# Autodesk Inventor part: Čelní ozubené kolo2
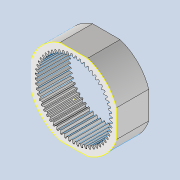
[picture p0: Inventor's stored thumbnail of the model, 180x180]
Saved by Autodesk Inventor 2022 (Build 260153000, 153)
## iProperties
CustomPartVersion: 1
Created: 2025-05
Part Number: Čelní ozubené kolo2
Material: Všeobecné
Document SubType Name: Modeling
Designer: jbart
Categories: <?xml version="1.0" encoding="UTF-16"?> <MemberInstance><Categories><FamilyTemplate><FamilyTemplateParameter ValueType="xs:double" Id="1" ObjectReferenceKey="da
Density: 1 g/cm^3
Appearance: Výchozí
Mass: 5402.18 g
Surface Area: 5816 cm^2
Volume: 5402.18 cm^3
Author: jbart
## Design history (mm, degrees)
sketch "Sketch1"
  geometry: C1 r 205 at (0, 0)
  constraints: 1 centre point
  dimensions: "d0" = 410 diameter of C1
extrude "Extrusion1" new body sketch "Sketch1" distance "d1" = 150 (= da_b); taper "d2" = 0 deg
workplane "Work Plane2"
sketch "Sketch2"
  geometry: C1 r 205 at (0, 0) reference; C2 r 171 at (0, 0)
  constraints: 1 centre point, 1 coincident
  dimensions: "d3" = 342 diameter of C2 (= da_d)
feature "Roztečný průměr" sketch "Sketch2" dims "d4" = 10, "d5" = 0
workplane "Work Plane8"
workplane "Work Plane9"
feature "Čelní ozubené kolo" dims "da_b" = 150, "da_d" = 342, "da_z" = 570, "da_aw" = 107.36314, "da_da" = 329.75677, "da_df" = 355.75525, "da_dw" = 339.98329, "da_z2" = 210, "da_beta" = 0, "da_lefttooth" = 0, "da_righttooth" = 0, "da_straighttooth" = 10
sketch "Náčrt5"
  geometry: L1 (0, 0)-(0, 50); L2 (-150, 215)-(150, 215); L3 (150, 215)-(150, 195); L4 (150, 195)-(-150, 195); L5 (-150, 195)-(-150, 215)
  constraints: 10 end point, 2 parallel, 1 horizontal, 1 perpendicular, 1 vertical, 1 other
  dimensions: "d60" = 50 distance of L1.start L1.end; "d61" = 300 distance of L3.end L4.end; "d62" = 20 distance of L2.end L3.end; "d63" = 195 distance from line of L1.start L4
extrude "Vysunutí3" cut sketch "Náčrt5" extent not by distance; stored distance "d64" = 0; taper "d65" = 0 deg
pattern_circular "Kruhové pole2" dims angle "d67" = 360 deg
body "Solid1"
body "Srf1"
other parameters: "d16" = 107.36314 (= da_aw), "d17" = 0, "d34" = 0.55116 (computed from da_z), "d39" = 0, "d45" = 0, "d47" = 107.36314 (= da_aw), "d50" = 0, "d51" = 0, "d52" = 107.36314 (= da_aw)
